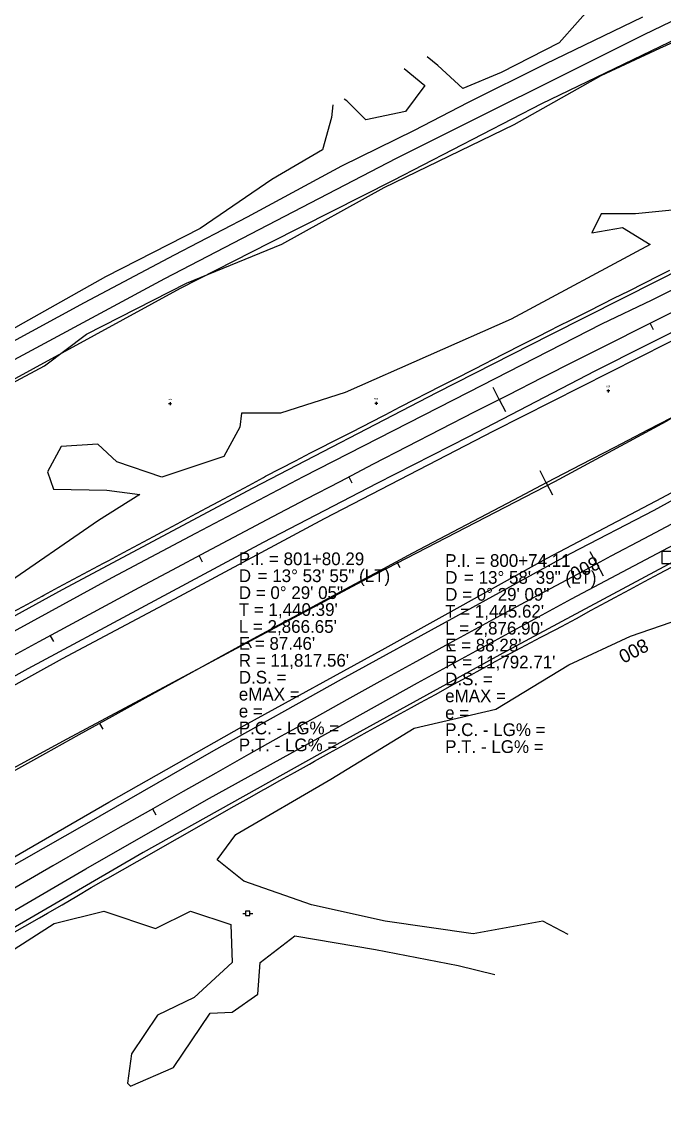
# Model space of a CAD drawing. Extents: x 1901471 to 1963503, y 756461 to 799997.
# Drawn here: x 1904101 to 1904480, y 758061 to 758713 of the extents above; entities that cross this region are included whole.
import ezdxf

# ---------------------------------------------------------------- set-up
doc = ezdxf.new("R2010")
doc.units = 0
for name, color, linetype in [('Default', 7, 'Continuous'), ('RD_DTM_BkLn1', 7, 'Continuous'), ('RD_EX_H2O', 7, 'Continuous'), ('RD_EX_Road', 7, 'Continuous'), ('RD_EX_UT', 7, 'Continuous'), ('RD_EX_VEG', 7, 'Continuous'), ('RD_HC_Cl', 7, 'Continuous'), ('RD_HC_Data', 7, 'Continuous'), ('RD_HC_Data_Tic', 7, 'Continuous'), ('RD_HC_Survey', 7, 'Continuous'), ('RD_HC_TX_Sta50', 7, 'Continuous')]:
    doc.layers.add(name, color=color, linetype=linetype)

# ---------------------------------------------------------------- blocks, each defined once
blk = doc.blocks.new('PP')
at = {"layer": 'RD_EX_UT'}
for p, q in [((2.5, 2.5), (-2.5, 2.5)), ((-2.5, 2.5), (-2.5, -2.5)), ((2.5, -2.5), (2.5, 2.5)), ((-5.9, -0.1), (-2.5, -0.1)), ((-2.5, -2.5), (2.5, -2.5)), ((2.4, -0.1), (6.1, -0.1))]:
    blk.add_line(p, q, dxfattribs=at)

msp = doc.modelspace()

# ---------------------------------------------------------------- linework, layer by layer
at = {"layer": 'Default'}
for p, q in [((1904448.33, 758494.99), (1904446.58, 758494.99)), ((1904447.45, 758495.86), (1904447.45, 758494.11)), ((1904189.24, 758487.45), (1904187.49, 758487.45)), ((1904188.36, 758488.33), (1904188.36, 758486.58)), ((1904311.15, 758487.58), (1904309.4, 758487.58)), ((1904310.28, 758488.45), (1904310.28, 758486.7))]:
    msp.add_line(p, q, dxfattribs=at)
at = {"layer": 'RD_DTM_BkLn1'}
for points in [[(1904095.22, 758364.18), (1904104, 758368.97), (1904112.78, 758373.76), (1904113.67, 758374.25), (1904122.49, 758378.96), (1904131.31, 758383.67), (1904140.14, 758388.38), (1904148.96, 758393.09), (1904152.09, 758394.76), (1904160.89, 758399.49), (1904169.7, 758404.23), (1904178.51, 758408.96), (1904183.66, 758411.73), (1904192.48, 758416.44), (1904201.31, 758421.15), (1904210.13, 758425.86), (1904217.25, 758429.66), (1904226.05, 758434.4), (1904234.85, 758439.15), (1904243.65, 758443.9), (1904244.83, 758444.53), (1904253.71, 758449.13), (1904262.59, 758453.73), (1904271.47, 758458.32), (1904276.55, 758460.96), (1904285.47, 758465.48), (1904294.39, 758470.01), (1904303.3, 758474.54), (1904306.71, 758476.26), (1904315.58, 758480.88), (1904324.44, 758485.5), (1904333.31, 758490.12), (1904340.21, 758493.71), (1904349.12, 758498.25), (1904358.03, 758502.79), (1904366.94, 758507.33), (1904375.85, 758511.87), (1904377.98, 758512.96), (1904386.9, 758517.49), (1904395.82, 758522.01), (1904404.73, 758526.54), (1904413.65, 758531.07), (1904417.45, 758533), (1904426.39, 758537.48), (1904435.32, 758541.97), (1904444.26, 758546.46), (1904450.79, 758549.74), (1904459.72, 758554.24), (1904468.65, 758558.75), (1904477.57, 758563.25), (1904483.85, 758566.42)], [(1904115.89, 758186.25), (1904124.52, 758191.29), (1904133.16, 758196.34), (1904141.8, 758201.38), (1904150.43, 758206.42), (1904151.5, 758207.04), (1904160.2, 758211.97), (1904168.9, 758216.9), (1904177.6, 758221.82), (1904184.08, 758225.49), (1904192.77, 758230.44), (1904201.47, 758235.38), (1904217.62, 758244.57), (1904226.33, 758249.48), (1904235.04, 758254.39), (1904243.75, 758259.3), (1904244.57, 758259.76), (1904253.3, 758264.65), (1904262.02, 758269.53), (1904270.75, 758274.41), (1904273.85, 758276.14), (1904282.59, 758281), (1904291.32, 758285.86), (1904300.06, 758290.72), (1904304.89, 758293.41), (1904313.65, 758298.23), (1904322.4, 758303.06), (1904331.16, 758307.89), (1904336.51, 758310.83), (1904345.28, 758315.64), (1904354.05, 758320.46), (1904361.23, 758324.4), (1904370.01, 758329.19), (1904378.79, 758333.98), (1904387.57, 758338.77), (1904389.91, 758340.05), (1904398.76, 758344.71), (1904407.6, 758349.38), (1904416.45, 758354.04), (1904419.8, 758355.81), (1904428.6, 758360.56), (1904437.41, 758365.31), (1904446.21, 758370.05), (1904451.3, 758372.8), (1904460.11, 758377.53), (1904468.92, 758382.26), (1904477.73, 758386.99), (1904484.87, 758390.83)], [(1904093.77, 758173.71), (1904102.47, 758178.64), (1904111.17, 758183.57), (1904115.89, 758186.25)]]:
    msp.add_lwpolyline(points, dxfattribs=at)
at = {"layer": 'RD_EX_H2O'}
msp.add_lwpolyline([(1904906.53, 758685.19), (1904786.85, 758628.56), (1904667.65, 758573.24), (1904559.15, 758517.45), (1904515.85, 758496.87), (1904502.05, 758489.49), (1904481.59, 758476.88), (1904415.68, 758441.19), (1904304.7, 758383.92), (1904127.28, 758289.07), (1904069.68, 758258.11), (1903982.87, 758204.42), (1903890.04, 758153.24), (1903843.88, 758124.39), (1903813.26, 758107.17)], dxfattribs=at)
at = {"layer": 'RD_EX_Road'}
for points in [[(1903647.51, 758104.6), (1903717.43, 758146.66), (1903827.32, 758210.89), (1903985.14, 758300.41), (1904059.41, 758341.71), (1904124.77, 758377.71), (1904237.5, 758437.77), (1904346.07, 758494.04), (1904413.14, 758528.14), (1904476.8, 758560.26), (1904503.89, 758574.09), (1904658.71, 758648.21), (1904783, 758706.77), (1904914.9, 758766.01), (1905034.39, 758818.03), (1905216.97, 758894.67), (1905301.21, 758929.29), (1905406.04, 758970.91), (1905520.94, 759016.05), (1905633.93, 759060.25), (1905824.57, 759132.97), (1905879.72, 759154.11), (1905899.75, 759161.72), (1906119.34, 759245.88)], [(1903672.83, 758077.8), (1903785.09, 758144.01), (1903851.74, 758183.4), (1903961.34, 758246.64), (1904053.46, 758297.44), (1904124.85, 758336.84), (1904194.16, 758373.72), (1904279.76, 758419.63), (1904379.88, 758471.32), (1904499.85, 758532.04), (1904656.83, 758608.02), (1904831.51, 758689.36), (1905038.39, 758781.42), (1905127.66, 758819.62), (1905303.64, 758891.51), (1905396.35, 758929.71), (1905570.17, 758997.31), (1905672.75, 759036.37), (1905899.8, 759123.07), (1906075.63, 759189.9)], [(1903629.25, 757935.1), (1903744.21, 758008.43), (1903839.03, 758066.36), (1903969.69, 758145.02), (1904044.66, 758189.76), (1904152.21, 758251.84), (1904232.21, 758297.32), (1904315.47, 758342.95), (1904410.88, 758395.84), (1904475.77, 758430.06), (1904499.77, 758442.8), (1904716.91, 758554.8), (1904840.53, 758616.18), (1904995.04, 758688.5), (1905159, 758763.82), (1905322.09, 758835.5), (1905449.14, 758888.08), (1905598.93, 758949.45), (1905763.32, 759013.62), (1905899.8, 759066.2), (1906068.03, 759131)], [(1906146.36, 759121.29), (1905900.23, 759028.43), (1905683.83, 758945.07), (1905509.3, 758874.76), (1905339.14, 758802.99), (1905228.72, 758755.05), (1905125.23, 758708.17), (1905011.45, 758655.76), (1904902.15, 758603.96), (1904794.64, 758551.66), (1904634.65, 758472), (1904568.65, 758437.49), (1904499.42, 758401.34), (1904387.32, 758341.09), (1904276.9, 758280.57), (1904172.52, 758222.06), (1904029.77, 758139.21), (1903914.76, 758070.52), (1903832.08, 758019.61), (1903783.86, 757989.97), (1903644.91, 757900.63)], [(1903754.56, 758321.98), (1903809.29, 758354.25), (1903872.68, 758391.68), (1903932.79, 758425.36), (1904002.5, 758463.14), (1904185.18, 758561.49), (1904322.25, 758632.48), (1904468.67, 758705.58), (1904531.83, 758736.22)], [(1904075.24, 758513.32), (1904137.84, 758547.34), (1904190.91, 758575.44), (1904234.06, 758597.99), (1904289.86, 758628.12), (1904332.82, 758649.21), (1904364.51, 758665.44), (1904410.39, 758688.38), (1904467.93, 758716.08)], [(1904499.61, 758708.89), (1904408.05, 758664.76), (1904320.18, 758619.37), (1904247.28, 758582.53), (1904194.41, 758555.61), (1904073.3, 758489.61)], [(1903665.72, 758105.79), (1903735.62, 758147.86), (1903805.23, 758189.18), (1903868.92, 758225.61), (1903958.67, 758277), (1904027.98, 758314.77), (1904087.23, 758348.24), (1904154.17, 758384.68), (1904203.64, 758410.89), (1904267.32, 758444.36), (1904364.78, 758494.28), (1904443.57, 758534.56), (1904473.49, 758548.93), (1904500.44, 758562.26)], [(1903638.76, 758062.84), (1903731.48, 758118.38), (1903795.46, 758155.71), (1903894.69, 758213.62), (1903966.08, 758254.05), (1904032.43, 758291.07), (1904104.41, 758330.92), (1904171.35, 758366.76), (1904243.63, 758405.56), (1904310.87, 758440.51), (1904365.07, 758468.06), (1904439.72, 758506.86), (1904499.55, 758537.08)], [(1903700.66, 757976.28), (1903748.66, 758006.65), (1903826.58, 758054.36), (1903922.29, 758112.58), (1904018.58, 758169.91), (1904087.92, 758210.21), (1904139.17, 758239.39), (1904214.14, 758282.36), (1904289.69, 758324.58), (1904357.25, 758361.62), (1904425.1, 758398.8), (1904474.58, 758424.58), (1904500.06, 758438.5)], [(1903641.69, 757909.32), (1903747.77, 757977.02), (1903817.69, 758021.02), (1903881.99, 758060.43), (1903977.1, 758117.76), (1904051.17, 758161.76), (1904138.58, 758212.43), (1904209.99, 758253.32), (1904285.55, 758295.1), (1904334.73, 758322.36), (1904425.69, 758372.13), (1904499.77, 758411.24)]]:
    msp.add_lwpolyline(points, dxfattribs=at)
at = {"layer": 'RD_EX_VEG'}
for points in [[(1904430.41, 758737.87), (1904440.07, 758725.19), (1904418.4, 758700.8), (1904384.07, 758683.19), (1904361.49, 758673.7), (1904346.59, 758687.25), (1904340.41, 758692.51)], [(1903985.76, 758441.35), (1904114.02, 758509.77), (1904138.85, 758528.51), (1904198.01, 758558.77), (1904254.46, 758581.8), (1904314.98, 758615.22), (1904391.75, 758652.48), (1904443.23, 758681.38), (1904478.01, 758697.64), (1904501.94, 758708.48)], [(1904326.83, 758685.58), (1904338.91, 758675.51), (1904327.62, 758660.15), (1904304.14, 758655.19), (1904292.85, 758666.48), (1904291.23, 758667.43)], [(1904284.52, 758664), (1904283.82, 758656.54), (1904278.4, 758637.57), (1904248.59, 758619.96), (1904206.14, 758591.06), (1904150.14, 758562.38), (1904081.05, 758523.54), (1904055.31, 758518.13), (1904044.92, 758519.48), (1904031.37, 758496.9), (1904006.53, 758489.67), (1903998.41, 758499.61), (1904018.28, 758513.16), (1904024.6, 758523.09), (1904025.89, 758526.04)], [(1904485.23, 758601.9), (1904463.56, 758599.64), (1904443.23, 758599.64), (1904437.81, 758588.35), (1904455.88, 758591.51), (1904472.14, 758581.58), (1904389.95, 758537.32), (1904291.95, 758493.96), (1904253.56, 758481.77), (1904230.53, 758481.77), (1904229.63, 758473.64), (1904220.14, 758456.26), (1904183.56, 758444.06), (1904156.92, 758453.09), (1904145.63, 758463.48), (1904123.95, 758462.13), (1904115.82, 758447.22), (1904119.44, 758436.84), (1904151.05, 758436.39), (1904170.47, 758433.68), (1904146.08, 758418.32), (1904088.27, 758378.58)], [(1904423.79, 758173.76), (1904408.8, 758181.47), (1904367.62, 758174.06), (1904315.47, 758181.47), (1904271.92, 758191.24), (1904231.92, 758205.17), (1904216.21, 758217.91), (1904227.17, 758232.87), (1904283.47, 758265.47), (1904332.66, 758295.69), (1904380.95, 758306.8), (1904424.21, 758333.17), (1904460.66, 758350.06), (1904484.66, 758358.21)], [(1904069.55, 758148.13), (1904119.92, 758180.28), (1904149.25, 758187.39), (1904179.77, 758177.32), (1904200.51, 758187.39), (1904224.21, 758179.69), (1904225.1, 758157.17), (1904202.58, 758136.43), (1904180.95, 758126.06), (1904165.55, 758103.24), (1904163.17, 758085.76), (1904164.95, 758084.13), (1904190.43, 758095.1), (1904212.06, 758127.1), (1904225.1, 758127.69), (1904240.21, 758138.36), (1904241.69, 758157.17), (1904262.14, 758172.87), (1904309.84, 758164.87), (1904358.73, 758155.39), (1904380.32, 758150.09)]]:
    msp.add_lwpolyline(points, dxfattribs=at)
at = {"layer": 'RD_HC_Cl'}
for centre, radius, start, end in [((1909748.74, 747960.74), 11817.56, 110.89447, 124.793002), ((1909868.32, 747986.81), 11792.71, 110.903407, 124.881023), ((1909948.59, 748094.28), 11678.9, 110.901971, 124.84852)]:
    msp.add_arc(centre, radius, start, end, dxfattribs=at)
at = {"layer": 'RD_HC_Data_Tic'}
for p, q in [((1904472.26, 758534.93), (1904474.04, 758531.35)), ((1904382.97, 758489.9), (1904379.34, 758497.03)), ((1904382.97, 758489.9), (1904386.6, 758482.77)), ((1904410.82, 758440.7), (1904407.11, 758447.79)), ((1904294.06, 758444.12), (1904295.91, 758440.57)), ((1904410.82, 758440.7), (1904414.52, 758433.61)), ((1904205.55, 758397.59), (1904207.43, 758394.06)), ((1904322.37, 758394.05), (1904324.25, 758390.52)), ((1904440.61, 758392.77), (1904436.84, 758399.82)), ((1904440.61, 758392.77), (1904444.38, 758385.72)), ((1904117.43, 758350.31), (1904119.34, 758346.79)), ((1904234.31, 758346.64), (1904236.23, 758343.13)), ((1904352.63, 758345.23), (1904354.55, 758341.72)), ((1904146.67, 758298.5), (1904148.61, 758295)), ((1904265.07, 758296.94), (1904267.01, 758293.45)), ((1904177.91, 758247.9), (1904179.89, 758244.42))]:
    msp.add_line(p, q, dxfattribs=at)
at = {"layer": 'RD_HC_Survey'}
msp.add_lwpolyline([(1904486.19, 758400.11), (1904479.11, 758400.11), (1904479.11, 758393.04), (1904486.19, 758393.04)], close=True, dxfattribs=at)

# ---------------------------------------------------------------- block references
at = {"layer": 'Default', "xscale": 0.5039370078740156, "yscale": 0.5039370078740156}
msp.add_blockref('PP', (1904234.29, 758186.21), dxfattribs=at)

# ---------------------------------------------------------------- texts
at = {"layer": 'Default'}
for s, p in [('538', (1904446.27, 758497.19)), ('523', (1904187.18, 758489.65)), ('509', (1904309.06, 758489.78))]:
    msp.add_text(s, height=1, dxfattribs=at).set_placement(p)
at = {"layer": 'RD_HC_Data'}
for s, p in [('P.I. = 801+80.29', (1904229, 758392)), ('P.I. = 800+74.11', (1904351, 758391)), ('D', (1904229, 758382)), ('    = 13%%d 53\' 55" (LT)', (1904229, 758382)), ('D', (1904351, 758381)), ('    = 13%%d 58\' 39" (LT)', (1904351, 758381)), ('D = 0%%d 29\' 05"', (1904229, 758372)), ('D = 0%%d 29\' 09"', (1904351, 758371)), ("T = 1,440.39'", (1904229, 758362)), ("T = 1,445.62'", (1904351, 758361)), ("L = 2,866.65'", (1904229, 758352)), ("L = 2,876.90'", (1904351, 758351)), ("E = 87.46'", (1904229, 758342)), ("E = 88.28'", (1904351, 758341)), ("R = 11,817.56'", (1904229, 758332)), ("R = 11,792.71'", (1904351, 758331)), ('D.S. = ', (1904229, 758322)), ('D.S. = ', (1904351, 758321)), ('eMAX = ', (1904229, 758312)), ('eMAX = ', (1904351, 758311)), ('e = ', (1904229, 758302)), ('e = ', (1904351, 758301)), ('P.C. - LG% = ', (1904229, 758292)), ('P.C. - LG% = ', (1904351, 758291)), ('P.T. - LG% = ', (1904229, 758282)), ('P.T. - LG% = ', (1904351, 758281))]:
    msp.add_text(s, height=7.5, dxfattribs=at).set_placement(p)
at = {"layer": 'RD_HC_TX_Sta50'}
for rotation, p in [(207.00389, (1904439.79, 758397.64)), (207.56703, (1904468.54, 758349))]:
    msp.add_text('800', height=8, rotation=rotation, dxfattribs=at).set_placement(p)

doc.saveas('drawing.dxf')
